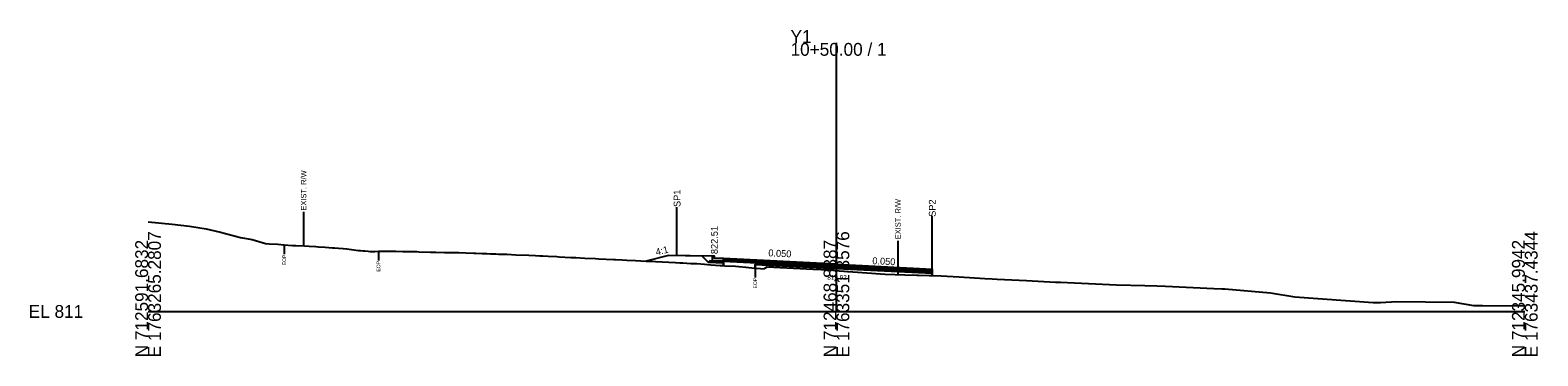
# Model space of a CAD drawing. Extents: x -26 to 1303, y -10 to 9524.
# Drawn here: x -25.7 to 302.8, y 490.3 to 561.4 of the extents above; entities that cross this region are included whole.
import ezdxf

# ---------------------------------------------------------------- set-up
doc = ezdxf.new("R2010")
doc.units = 0
for name, color, linetype in [('Default', 7, 'Continuous'), ('Exist Cross Section Cell', 7, 'Continuous'), ('Exist XS Center Line Elevation Label', 7, 'Continuous'), ('Exist XS Ground Line', 7, 'Continuous'), ('Old_Level_10', 7, 'Continuous'), ('Prop CMT Conc Surface', 7, 'Continuous'), ('Prop CMT Concrete Structures', 7, 'Continuous'), ('Prop CMT Pvmt Course 1', 7, 'Continuous'), ('Prop CMT Pvmt Course 1 CG', 7, 'Continuous'), ('Prop CMT Pvmt Course 2', 7, 'Continuous'), ('Prop CMT Pvmt Course 3', 7, 'Continuous'), ('Prop CMT Pvmt Surface', 7, 'Continuous'), ('Prop CMT Slope Grass', 7, 'Continuous'), ('Prop CMT Subgrade Earthwork', 7, 'Continuous'), ('Prop XS Earthwork Shape', 7, 'Continuous'), ('Prop XS Hydro Elevations', 7, 'Continuous'), ('Prop XS SE Text', 7, 'Continuous'), ('Prop XS Shear Point Element', 7, 'Continuous'), ('Prop XS Side Slope Text', 7, 'Continuous')]:
    doc.layers.add(name, color=color, linetype=linetype)

msp = doc.modelspace()

# ---------------------------------------------------------------- linework, layer by layer
at = {"layer": 'Exist Cross Section Cell'}
for p, q in [((150, 500), (150, 558.56)), ((0, 500), (150, 500)), ((150, 500), (300, 500))]:
    msp.add_line(p, q, dxfattribs=at)
at = {"layer": 'Exist XS Ground Line'}
msp.add_lwpolyline([(0, 519.52), (5.24, 519.06), (9.03, 518.58), (12.67, 518.05), (15.81, 517.26), (20.14, 516.16), (22.67, 515.68), (25.58, 514.84), (26.42, 514.77), (28.26, 514.69), (29.68, 514.53), (31.49, 514.4), (32.19, 514.36), (34.11, 514.28), (35.11, 514.23), (36.54, 514.15), (37.16, 514.11), (38.61, 514.01), (40.21, 513.89), (40.66, 513.87), (41.51, 513.83), (42.49, 513.75), (43.33, 513.65), (45.82, 513.32), (46.32, 513.27), (46.89, 513.21), (47.26, 513.19), (47.94, 513.12), (48.39, 513.08), (49.4, 513.06), (50.2, 513.14), (51.45, 513.15), (52.42, 513.15), (53.97, 513.13), (55.48, 513.1), (58.53, 513.04), (59.01, 513.03), (61.58, 512.95), (62.03, 512.93), (62.68, 512.91), (64.63, 512.86), (67.04, 512.83), (67.69, 512.82), (69.21, 512.77), (71.01, 512.71), (71.39, 512.69), (72.8, 512.65), (73.79, 512.62), (74.6, 512.59), (75.75, 512.54), (76.39, 512.51), (76.84, 512.5), (78.19, 512.46), (80.11, 512.37), (82.95, 512.24), (84.46, 512.17), (85.37, 512.13), (86, 512.1), (87.16, 512.05), (89.06, 511.97), (89.61, 511.94), (92.11, 511.79), (93.18, 511.73), (95.16, 511.64), (97.53, 511.52), (98.21, 511.49), (99.8, 511.42), (101.52, 511.35), (101.89, 511.32), (103.32, 511.22), (104.32, 511.18), (106.25, 511.09), (107.37, 511.04), (108.7, 510.98), (110.6, 510.9), (113.48, 510.75), (114.96, 510.67), (115.88, 510.62), (116.53, 510.58), (118.24, 510.48), (119.58, 510.42), (121.27, 510.3), (122.63, 510.19), (123.67, 510.11), (125.69, 509.98), (128.03, 509.84), (128.74, 509.78), (130.24, 509.66), (131.53, 509.51), (132.27, 509.45), (133.43, 509.36), (134.23, 509.29), (134.54, 509.51), (134.87, 509.74), (144.91, 509.21), (146.73, 509.11), (148.01, 509.07), (148.4, 509.05), (150, 508.92), (150.59, 508.87), (160.61, 508.11), (164.89, 507.99), (172.82, 507.76), (176.73, 507.53), (182.32, 507.2), (183.91, 507.11), (185.03, 507.06), (191.39, 506.77), (197.71, 506.36), (198.79, 506.35), (211.06, 505.77), (217.17, 505.66), (219.82, 505.58), (221.67, 505.48), (232.2, 505), (234.08, 504.9), (234.6, 504.9), (244.6, 504.03), (249.89, 503.2), (266.92, 501.95), (268.57, 501.93), (272.11, 502.18), (284.59, 501.99), (288.79, 501.33), (290.77, 501.31), (300, 501.19)], dxfattribs=at)
at = {"layer": 'Old_Level_10'}
for p, q in [((33.9, 521.69), (33.9, 514.29)), ((29.68, 514.53), (29.68, 512.48)), ((50.2, 513.14), (50.2, 511.09)), ((163.41, 515.43), (163.41, 508.03)), ((132.27, 509.45), (132.27, 507.4))]:
    msp.add_line(p, q, dxfattribs=at)
at = {"layer": 'Prop CMT Conc Surface'}
for points in [[(123.4, 511.52), (123.4, 512.02), (122.9, 512.02)], [(125.4, 511.52), (123.4, 511.52)]]:
    msp.add_lwpolyline(points, dxfattribs=at)
at = {"layer": 'Prop CMT Concrete Structures'}
for points in [[(125.4, 511.52), (123.4, 511.52), (123.4, 512.02), (122.9, 512.02)], [(122.9, 512.02), (122.9, 511.03), (125.4, 510.93)], [(125.4, 510.93), (125.4, 511.52)]]:
    msp.add_lwpolyline(points, dxfattribs=at)
at = {"layer": 'Prop CMT Pvmt Course 1'}
for points in [[(150, 510.29), (125.4, 511.52)], [(125.4, 511.52), (125.4, 511.27)], [(125.4, 511.52), (125.4, 511.27)], [(125.4, 511.27), (150, 510.04)], [(150, 510.04), (150, 510.29)], [(150, 510.29), (170.86, 509.25)], [(150, 510.04), (150, 510.04), (150, 510.04), (150, 510.04), (150, 510.04)], [(170.86, 509), (150, 510.04)]]:
    msp.add_lwpolyline(points, dxfattribs=at)
msp.add_lwpolyline([(150, 510.04), (150, 510.04), (150, 510.04), (150, 510.04)], close=True, dxfattribs=at)
at = {"layer": 'Prop CMT Pvmt Course 1 CG'}
for points in [[(125.4, 510.93), (122.4, 511.05), (122.08, 510.73)], [(122.08, 510.74), (125.4, 510.6)]]:
    msp.add_lwpolyline(points, dxfattribs=at)
at = {"layer": 'Prop CMT Pvmt Course 2'}
for points in [[(150, 510.04), (125.4, 511.27)], [(125.4, 511.27), (125.4, 510.93)], [(125.4, 511.27), (125.4, 510.93)], [(125.4, 510.94), (150, 509.71)], [(150, 509.71), (150, 510.04)], [(150, 509.71), (150, 510.04)], [(150, 510.04), (170.86, 509)], [(170.86, 508.66), (150, 509.71)]]:
    msp.add_lwpolyline(points, dxfattribs=at)
at = {"layer": 'Prop CMT Pvmt Course 3'}
for points in [[(150, 509.71), (125.4, 510.94)], [(132.27, 510.26), (150, 509.37)], [(150, 509.38), (150, 509.71)], [(150, 509.38), (150, 509.71)], [(150, 509.71), (170.86, 508.66)], [(170.86, 508.33), (150, 509.37)]]:
    msp.add_lwpolyline(points, dxfattribs=at)
at = {"layer": 'Prop CMT Pvmt Surface'}
msp.add_line((170.86, 509.25), (170.86, 507.82), dxfattribs=at)
for points in [[(150, 510.29), (125.4, 511.52)], [(150, 510.29), (170.86, 509.25)]]:
    msp.add_lwpolyline(points, dxfattribs=at)
at = {"layer": 'Prop CMT Slope Grass'}
for points in [[(113.4, 512.21), (108.52, 510.99)], [(122.9, 512.02), (113.4, 512.21)]]:
    msp.add_lwpolyline(points, dxfattribs=at)
at = {"layer": 'Prop CMT Subgrade Earthwork'}
for p, q in [((125.4, 510.6), (125.4, 510)), ((132.27, 509.45), (132.27, 510.26)), ((170.86, 508.33), (170.86, 507.82))]:
    msp.add_line(p, q, dxfattribs=at)
for points in [[(125.4, 510.6), (122.08, 510.74), (120.75, 512.06)], [(150, 509.37), (132.27, 510.26)], [(150, 509.37), (170.86, 508.33)]]:
    msp.add_lwpolyline(points, dxfattribs=at)
at = {"layer": 'Prop XS Earthwork Shape'}
for points in [[(120.75, 512.06), (113.4, 512.21), (108.52, 510.99), (108.7, 510.98), (110.6, 510.9), (113.48, 510.75), (114.96, 510.67), (115.88, 510.62), (116.53, 510.58), (118.24, 510.48), (119.58, 510.42), (121.27, 510.3), (122.63, 510.19), (123.67, 510.11), (125.4, 510), (125.4, 510.6), (122.08, 510.74)], [(146.73, 509.11), (148.01, 509.07), (148.4, 509.05), (150, 508.92), (150.59, 508.87), (160.61, 508.11), (164.89, 507.99), (170.86, 507.82), (170.86, 508.33), (150, 509.37), (132.27, 510.26), (132.27, 509.45), (133.43, 509.36), (134.23, 509.29), (134.54, 509.51), (134.87, 509.74), (144.91, 509.21)]]:
    msp.add_lwpolyline(points, close=True, dxfattribs=at)
at = {"layer": 'Prop XS Shear Point Element'}
for p, q in [((115.24, 512.16), (115.24, 522.77)), ((170.86, 509.25), (170.86, 520.84))]:
    msp.add_line(p, q, dxfattribs=at)

# ---------------------------------------------------------------- texts
at = {"layer": 'Default'}
msp.add_text('-', height=0.0001, dxfattribs=at).set_placement((0, 500))
at = {"layer": 'Exist Cross Section Cell'}
for s, p in [('Y1', (140, 558.56)), ('10+50.00 / 1', (140, 555.76)), ('EL 811', (-26, 498.6))]:
    msp.add_text(s, height=2.8, dxfattribs=at).set_placement(p)
for s, p in [('E 1763265.2807', (2.8, 490)), ('E 1763351.3576', (152.8, 490)), ('E 1763437.4344', (302.8, 490)), ('N 712591.6832', (0, 490)), ('N 712468.8387', (150, 490)), ('N 712345.9942', (300, 490))]:
    msp.add_text(s, height=2.8, rotation=90, dxfattribs=at).set_placement(p)
at = {"layer": 'Exist XS Center Line Elevation Label'}
msp.add_text('819.92', height=1, dxfattribs=at).set_placement((148.01, 506.92))
at = {"layer": 'Old_Level_10'}
for s, height, p in [('EXIST. R/W', 1.181, (34.49, 521.99)), ('EXIST. R/W', 1.181, (164, 515.74)), ('EOP', 0.787, (30.07, 510.08)), ('EOP', 0.787, (50.59, 508.69)), ('EOP', 0.787, (132.67, 505))]:
    msp.add_text(s, height=height, rotation=90, dxfattribs=at).set_placement(p)
at = {"layer": 'Prop XS Hydro Elevations'}
msp.add_text('822.51', height=1.5, rotation=90, dxfattribs=at).set_placement((124.15, 512.5))
at = {"layer": 'Prop XS SE Text'}
for p in [(135.13, 512.04), (157.79, 510.32)]:
    msp.add_text('0.050', height=1.5, rotation=357.1376, dxfattribs=at).set_placement(p)
at = {"layer": 'Prop XS Shear Point Element'}
for s, p in [('SP1', (116.02, 522.78)), ('SP2', (171.64, 520.63))]:
    msp.add_text(s, height=1.5, rotation=90, dxfattribs=at).set_placement(p)
at = {"layer": 'Prop XS Side Slope Text'}
msp.add_text('4:1', height=1.5, rotation=14.0362, dxfattribs=at).set_placement((110.8, 512.18))

doc.saveas('drawing.dxf')
